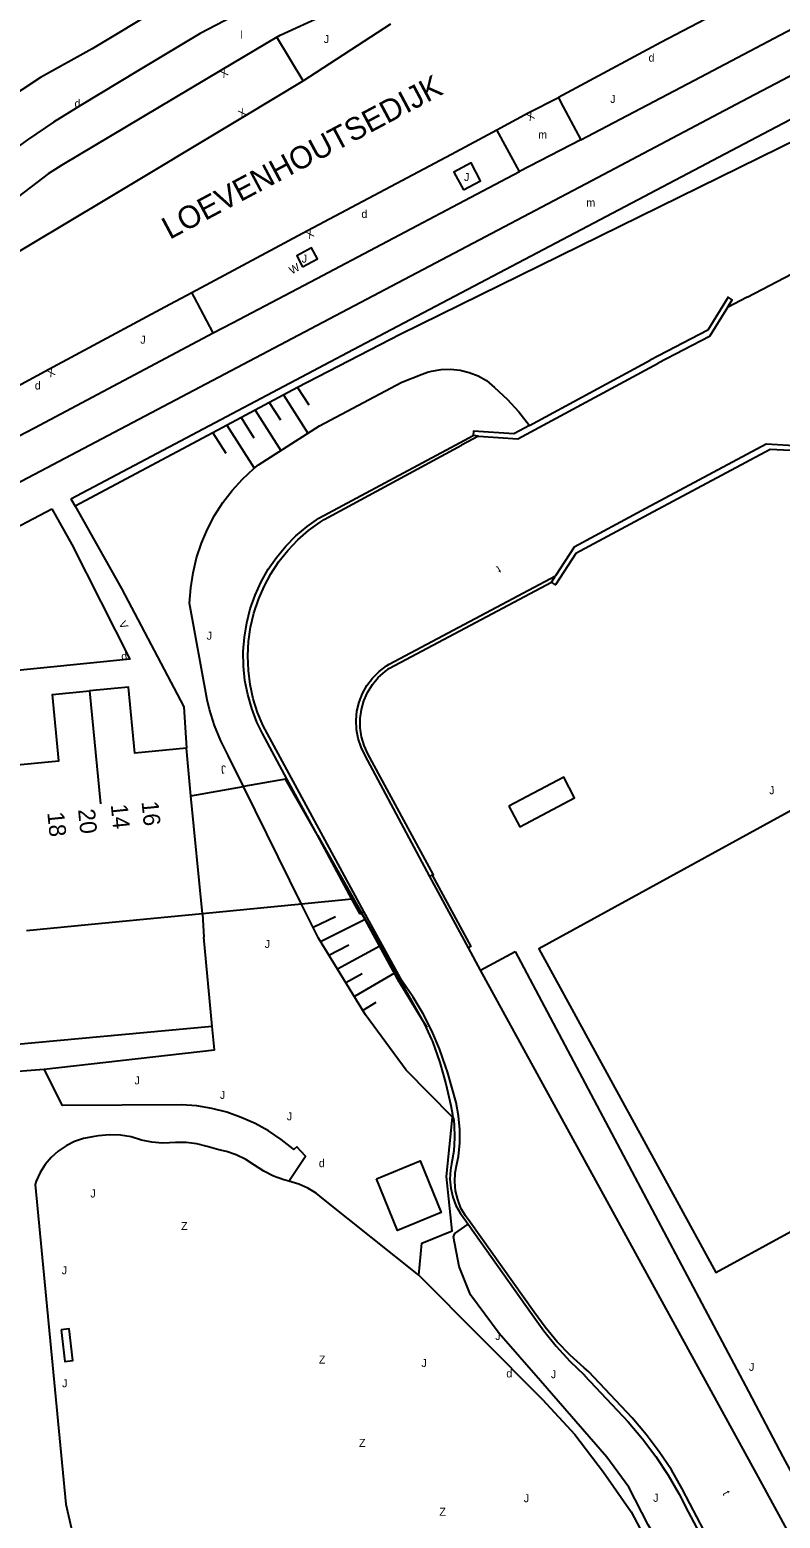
# Model space of a CAD drawing. Extents: x 134999 to 136502, y 457398 to 459002.
# Drawn here: x 136033.6 to 136080.5, y 457701.1 to 457794.1 of the extents above; entities that cross this region are included whole.
import ezdxf

# ---------------------------------------------------------------- set-up
doc = ezdxf.new("R2010")
doc.units = 0
for name, color, linetype in [('RI_DGTB_15', 7, 'Continuous'), ('RI_DGTB_18', 7, 'Continuous'), ('RI_DGTB_2', 7, 'Continuous'), ('RI_DGTB_29', 7, 'Continuous'), ('RI_DGTB_30', 7, 'Continuous'), ('RI_DGTB_31', 7, 'Continuous'), ('RI_DGTB_32', 7, 'Continuous'), ('RI_DGTB_35', 7, 'Continuous'), ('RI_DGTB_36', 7, 'Continuous'), ('RI_DGTB_37', 7, 'Continuous'), ('RI_DGTB_4', 7, 'Continuous'), ('RI_DGTB_43', 7, 'Continuous'), ('RI_DGTB_48', 7, 'Continuous'), ('RI_DGTB_49', 7, 'Continuous'), ('RI_DGTB_53', 7, 'Continuous'), ('RI_DGTB_54', 7, 'Continuous'), ('RI_DGTB_58', 7, 'Continuous'), ('RI_DGTB_6', 7, 'Continuous')]:
    doc.layers.add(name, color=color, linetype=linetype)

msp = doc.modelspace()

# ---------------------------------------------------------------- linework, layer by layer
at = {"layer": 'RI_DGTB_15'}
msp.add_line((136037.37, 457752.745), (136038.06, 457745.695), dxfattribs=at)
at = {"layer": 'RI_DGTB_18'}
for p, q in [((136049.494, 457771.241), (136051.018, 457768.855)), ((136050.378, 457771.713), (136051.077, 457770.619)), ((136047.728, 457770.296), (136049.335, 457767.781)), ((136048.61, 457770.772), (136049.305, 457769.684)), ((136045.956, 457769.359), (136047.651, 457766.707)), ((136046.845, 457769.826), (136047.65, 457768.566)), ((136045.078, 457768.883), (136045.898, 457767.6)), ((136050.625, 457739.432), (136046.998, 457746.769)), ((136052.745, 457738.628), (136051.357, 457737.97)), ((136054.604, 457738.462), (136051.81, 457737.077)), ((136053.579, 457736.861), (136052.337, 457736.219)), ((136055.516, 457736.792), (136052.87, 457735.36)), ((136061.812, 457735.294), (136063.968, 457736.473)), ((136054.42, 457735.078), (136053.4, 457734.504)), ((136056.429, 457735.111), (136053.925, 457733.643)), ((136055.264, 457733.284), (136054.451, 457732.786)), ((136060.05, 457726.105), (136060.113, 457726.041))]:
    msp.add_line(p, q, dxfattribs=at)
for points in [[(136106.177, 457800), (136085.466, 457789.129), (136056.796, 457775.016)], [(136056.796, 457775.016), (136050.378, 457771.713), (136045.078, 457768.883), (136036.475, 457764.296)], [(136058.167, 457772.539), (136058.497, 457772.667), (136058.753, 457772.736), (136059.34, 457772.833), (136059.934, 457772.851), (136060.526, 457772.789), (136061.103, 457772.649), (136061.657, 457772.432), (136062.177, 457772.143), (136062.692, 457771.714), (136063.475, 457770.977), (136064.2, 457770.185), (136064.864, 457769.341)], [(136046.998, 457746.769), (136046.035, 457748.712), (136045.574, 457749.636), (136045.186, 457750.593), (136044.873, 457751.578), (136044.72, 457752.186), (136043.632, 457758.228), (136043.698, 457759.184), (136043.843, 457760.132), (136044.067, 457761.064), (136044.367, 457761.975), (136044.743, 457762.857), (136045.19, 457763.705), (136045.707, 457764.512), (136046.289, 457765.274), (136046.933, 457765.984), (136047.634, 457766.639), (136047.927, 457766.882), (136051.737, 457769.313), (136056.882, 457772.041), (136058.167, 457772.539)], [(136060.05, 457726.105), (136057.171, 457729.051), (136054.631, 457732.501), (136051.677, 457737.292), (136050.625, 457739.432)], [(136063.968, 457736.473), (136078.546, 457708.97), (136080.695, 457704.886), (136101.064, 457667.235), (136120.849, 457630.867), (136122.138, 457628.364), (136122.744, 457627.053)], [(136123.733, 457602.393), (136120.854, 457608.26), (136113.226, 457622.174), (136108.621, 457631.115), (136104.943, 457638.994), (136101.264, 457646.446), (136083.989, 457678.217), (136077.85, 457689.911), (136077.399, 457690.806), (136074.236, 457697.397), (136072.278, 457700.64), (136071.067, 457702.994), (136069.704, 457704.875), (136065.561, 457709.646), (136062.974, 457712.597), (136061.189, 457715.009), (136060.471, 457716.789), (136060.125, 457718.639), (136060.201, 457718.837), (136061.046, 457719.422)]]:
    msp.add_lwpolyline(points, dxfattribs=at)
at = {"layer": 'RI_DGTB_2'}
msp.add_lwpolyline([(136096.988, 457758.601), (136096.548, 457759.448), (136091.535, 457756.892), (136093.868, 457752.395), (136088.931, 457749.695), (136089.018, 457749.537), (136065.444, 457736.642), (136076.51, 457716.41), (136097.04, 457727.64), (136100.779, 457725.365)], dxfattribs=at)
at = {"layer": 'RI_DGTB_32'}
msp.add_lwpolyline([(136035.608, 457712.829), (136035.839, 457710.846), (136036.336, 457710.904), (136036.105, 457712.887), (136035.608, 457712.829)], dxfattribs=at)
at = {"layer": 'RI_DGTB_4'}
for p, q in [((136043.716, 457746.202), (136043.426, 457749.167)), ((136044.436, 457738.829), (136043.716, 457746.202)), ((136044.436, 457738.829), (136038.786, 457738.278)), ((136038.786, 457738.278), (136033.434, 457737.757))]:
    msp.add_line(p, q, dxfattribs=at)
for points in [[(136032.42, 457748.095), (136035.457, 457748.389), (136035.055, 457752.518), (136037.37, 457752.745)], [(136043.426, 457749.167), (136040.206, 457748.853), (136039.808, 457752.985), (136037.37, 457752.745)]]:
    msp.add_lwpolyline(points, dxfattribs=at)
at = {"layer": 'RI_DGTB_48'}
for p, q in [((136043.716, 457746.202), (136046.998, 457746.769)), ((136051.619, 457743.727), (136054.38, 457738.871)), ((136050.625, 457739.432), (136044.436, 457738.829)), ((136053.776, 457739.739), (136050.625, 457739.432)), ((136044.436, 457738.829), (136044.512, 457737.353)), ((136054.38, 457738.871), (136056.832, 457734.569)), ((136045.047, 457731.785), (136044.512, 457737.353)), ((136056.832, 457734.569), (136058.171, 457732.193)), ((136058.171, 457732.193), (136058.449, 457731.727)), ((136060.067, 457726.277), (136060.05, 457726.105))]:
    msp.add_line(p, q, dxfattribs=at)
for points in [[(136051.619, 457743.727), (136049.629, 457747.224), (136046.998, 457746.769)], [(136057.944, 457716.231), (136058.149, 457718.239), (136060.038, 457719.005), (136059.673, 457722.41), (136060.05, 457726.105)], [(136049.835, 457722.112), (136049.508, 457722.197), (136048.868, 457722.429), (136048.26, 457722.735), (136047.691, 457723.11), (136047.139, 457723.467), (136046.547, 457723.754), (136045.925, 457723.967), (136045.456, 457724.074), (136044.729, 457724.288), (136044.079, 457724.45), (136043.414, 457724.533), (136042.745, 457724.536), (136042.369, 457724.503), (136041.946, 457724.495), (136041.277, 457724.549), (136040.619, 457724.681), (136039.981, 457724.89), (136039.305, 457724.993), (136038.623, 457725.015), (136037.942, 457724.957), (136037.569, 457724.891), (136036.991, 457724.78), (136036.434, 457724.591), (136035.907, 457724.329), (136035.421, 457723.998), (136034.984, 457723.603), (136034.605, 457723.154), (136034.29, 457722.657), (136034.045, 457722.121), (136033.971, 457721.909), (136035.903, 457701.937), (136036.459, 457699.463)], [(136057.944, 457716.231), (136052.002, 457720.983), (136051.529, 457721.366), (136051.011, 457721.683), (136050.455, 457721.93), (136049.835, 457722.112)], [(136057.944, 457716.231), (136065.689, 457708.481), (136067.693, 457706.277), (136069.486, 457703.938), (136071.216, 457701.453), (136071.805, 457700.347)]]:
    msp.add_lwpolyline(points, dxfattribs=at)
at = {"layer": 'RI_DGTB_49'}
msp.add_line((136058.449, 457731.727), (136058.421, 457731.701), dxfattribs=at)
at = {"layer": 'RI_DGTB_53'}
for p, q in [((136050.832, 457797.257), (136044.288, 457793.823)), ((136040.445, 457791.524), (136036.821, 457789.33)), ((136068.066, 457787.192), (136064.239, 457785.208)), ((136068.066, 457787.192), (136068.464, 457787.402)), ((136021.213, 457756.888), (136035.021, 457764.132))]:
    msp.add_line(p, q, dxfattribs=at)
for points in [[(136023.793, 457760.97), (136035.091, 457766.906), (136052.351, 457776.008), (136068.76, 457784.651), (136078.139, 457789.59), (136097.898, 457800)], [(136036.214, 457764.759), (136053.5, 457773.888), (136069.286, 457782.2), (136079.053, 457787.349), (136103.086, 457800)], [(136068.464, 457787.402), (136075.569, 457791.121), (136092.362, 457800)], [(136049.083, 457793.609), (136049.284, 457793.716), (136052.011, 457794.975)], [(136050.725, 457790.861), (136056.214, 457794.422)], [(136049.083, 457793.609), (136045.634, 457791.566), (136035.653, 457785.595), (136034.796, 457785.055), (136029.996, 457781.421)], [(136044.288, 457793.823), (136040.445, 457791.524)], [(136050.725, 457790.861), (136049.083, 457793.609)], [(136031.342, 457779.255), (136038.36, 457783.439), (136047.069, 457788.662), (136050.725, 457790.861)], [(136062.826, 457787.812), (136064.791, 457788.87), (136066.672, 457789.822)], [(136066.672, 457789.822), (136066.799, 457789.562), (136068.066, 457787.192)], [(136036.821, 457789.33), (136035.134, 457788.293), (136033.492, 457787.188), (136032.97, 457786.817)], [(136043.771, 457777.645), (136051.005, 457781.51), (136059.996, 457786.287), (136062.826, 457787.812)], [(136064.239, 457785.208), (136062.826, 457787.812)], [(136045.108, 457775.127), (136046.315, 457775.754), (136051.193, 457778.319), (136060.801, 457783.384), (136064.239, 457785.208)], [(136060.742, 457784.056), (136061.811, 457784.625), (136061.219, 457785.738), (136060.149, 457785.168), (136060.742, 457784.056)], [(136050.69, 457779.242), (136051.619, 457779.744), (136051.249, 457780.427), (136050.321, 457779.925), (136050.69, 457779.242)], [(136018.82, 457763.992), (136023.265, 457766.478), (136032.877, 457771.782), (136034.83, 457772.846), (136042.086, 457776.755), (136043.771, 457777.645)], [(136045.108, 457775.127), (136043.908, 457777.374), (136043.771, 457777.645)], [(136020.028, 457761.958), (136021.069, 457762.527), (136022.582, 457763.287), (136033.931, 457769.19), (136045.108, 457775.127)], [(136036.214, 457764.759), (136036.475, 457764.296)], [(136035.021, 457764.132), (136036.275, 457761.907)], [(136036.475, 457764.296), (136039.379, 457759.144)]]:
    msp.add_lwpolyline(points, dxfattribs=at)
at = {"layer": 'RI_DGTB_54'}
msp.add_line((136031.845, 457728.904), (136034.552, 457729.111), dxfattribs=at)
for points in [[(136049.819, 457800), (136043.73, 457796.624), (136041.882, 457795.467), (136037.542, 457792.862), (136034.323, 457791.076), (136030.788, 457788.763), (136026.961, 457786.044), (136020.907, 457780.612), (136016.279, 457776.789)], [(136086.028, 457800), (136079.534, 457796.67), (136073.076, 457793.27), (136066.672, 457789.822)], [(136036.275, 457761.907), (136039.898, 457754.737), (136021.074, 457752.839), (136020.823, 457755.06)], [(136039.379, 457759.144), (136043.274, 457751.751), (136043.426, 457749.167)], [(136045.047, 457731.785), (136023.134, 457729.758), (136022.437, 457736.685)], [(136034.552, 457729.111), (136045.182, 457730.316), (136045.047, 457731.785)], [(136049.835, 457722.112), (136050.864, 457723.67), (136050.333, 457724.256), (136050.149, 457724.086), (136050.099, 457724.13), (136049.351, 457724.723), (136048.556, 457725.252), (136047.719, 457725.712), (136046.847, 457726.101), (136045.946, 457726.416), (136045.021, 457726.654), (136044.079, 457726.814), (136043.128, 457726.894), (136035.696, 457726.84), (136034.552, 457729.111)]]:
    msp.add_lwpolyline(points, dxfattribs=at)
at = {"layer": 'RI_DGTB_58'}
for p, q in [((136078.46, 457777.349), (136121.852, 457800)), ((136078.46, 457777.349), (136077.242, 457776.713)), ((136064.864, 457769.341), (136072.413, 457773.421)), ((136060.527, 457768.278), (136061.342, 457768.705)), ((136061.672, 457768.666), (136060.625, 457768.1)), ((136061.672, 457768.666), (136061.342, 457768.705)), ((136066.245, 457759.544), (136066.498, 457759.936)), ((136051.619, 457743.727), (136049.713, 457747.252)), ((136053.776, 457739.739), (136051.619, 457743.727)), ((136058.784, 457741.225), (136058.639, 457741.159)), ((136061.047, 457736.69), (136058.639, 457741.159)), ((136054.28, 457738.807), (136053.776, 457739.739)), ((136054.28, 457738.807), (136054.38, 457738.871)), ((136054.38, 457738.871), (136054.519, 457738.97)), ((136056.746, 457734.521), (136054.38, 457738.871)), ((136056.91, 457734.618), (136054.519, 457738.97)), ((136061.812, 457735.294), (136061.047, 457736.69)), ((136056.746, 457734.521), (136056.832, 457734.569)), ((136056.746, 457734.521), (136058.171, 457732.193)), ((136056.832, 457734.569), (136056.91, 457734.618)), ((136058.171, 457732.193), (136058.421, 457731.701)), ((136060.113, 457726.041), (136060.067, 457726.277))]:
    msp.add_line(p, q, dxfattribs=at)
for points in [[(136077.242, 457776.713), (136077.537, 457777.191), (136077.282, 457777.348), (136076.007, 457775.281), (136072.413, 457773.421)], [(136077.242, 457776.713), (136076.116, 457774.887), (136072.915, 457773.232)], [(136061.672, 457768.666), (136064.146, 457768.498), (136072.915, 457773.232)], [(136064.864, 457769.341), (136063.892, 457768.816), (136061.369, 457768.987), (136061.342, 457768.705)], [(136049.713, 457747.252), (136048.183, 457750.081), (136047.835, 457750.801), (136047.509, 457751.646), (136047.26, 457752.516), (136047.088, 457753.404), (136046.995, 457754.305), (136046.983, 457755.21), (136047.05, 457756.113), (136047.196, 457757.006), (136047.421, 457757.883), (136047.722, 457758.737), (136048.098, 457759.56), (136048.544, 457760.348), (136049.059, 457761.093), (136049.637, 457761.789), (136050.274, 457762.432), (136050.966, 457763.016), (136051.706, 457763.537), (136060.527, 457768.278)], [(136081.767, 457768.041), (136079.65, 457768.157), (136072.141, 457764.149)], [(136054.519, 457738.97), (136048.218, 457750.569), (136047.874, 457751.401), (136047.605, 457752.26), (136047.413, 457753.14), (136047.3, 457754.033), (136047.267, 457754.933), (136047.313, 457755.832), (136047.439, 457756.723), (136047.644, 457757.6), (136047.926, 457758.455), (136048.283, 457759.282), (136048.711, 457760.074), (136049.208, 457760.825), (136049.77, 457761.528), (136050.392, 457762.179), (136051.069, 457762.773), (136051.797, 457763.303), (136052.043, 457763.462), (136060.625, 457768.1)], [(136081.767, 457768.041), (136082.419, 457768.005), (136082.403, 457767.705), (136079.909, 457767.842), (136072.298, 457763.781)], [(136072.298, 457763.781), (136067.755, 457761.325), (136066.497, 457759.381), (136066.245, 457759.544)], [(136072.141, 457764.149), (136067.656, 457761.726), (136066.498, 457759.936)], [(136058.639, 457741.159), (136054.606, 457748.708), (136054.349, 457749.225), (136054.167, 457749.772), (136054.061, 457750.34), (136054.035, 457750.916), (136054.089, 457751.491), (136054.221, 457752.053), (136054.43, 457752.591), (136054.712, 457753.095), (136055.06, 457753.555), (136055.468, 457753.963), (136055.929, 457754.31), (136056.102, 457754.417), (136066.498, 457759.936)], [(136058.784, 457741.225), (136058.863, 457741.261), (136054.768, 457748.815), (136054.533, 457749.336), (136054.373, 457749.884), (136054.291, 457750.45), (136054.289, 457751.021), (136054.367, 457751.587), (136054.523, 457752.137), (136054.754, 457752.659), (136055.055, 457753.145), (136055.422, 457753.583), (136055.846, 457753.966), (136056.127, 457754.168), (136066.245, 457759.544)], [(136058.784, 457741.225), (136061.2, 457736.776), (136061.047, 457736.69)], [(136121.392, 457626.305), (136098.946, 457667.306), (136079.053, 457703.844), (136061.812, 457735.294)], [(136084.948, 457682.81), (136074.89, 457701.98), (136074.417, 457702.896), (136073.732, 457704.069), (136072.979, 457705.199), (136072.161, 457706.283), (136071.281, 457707.317), (136068.572, 457710.21), (136068.291, 457710.443), (136067.42, 457711.233), (136066.605, 457712.081), (136065.849, 457712.982), (136065.156, 457713.932), (136061.165, 457719.553), (136060.867, 457719.946), (136060.588, 457720.436), (136060.382, 457720.96), (136060.252, 457721.508), (136060.2, 457722.069), (136060.229, 457722.632), (136060.337, 457723.185), (136060.422, 457723.66), (136060.508, 457724.502), (136060.515, 457725.349), (136060.441, 457726.193), (136060.289, 457727.026), (136059.741, 457728.945), (136059.65, 457729.243), (136059.246, 457730.386), (136058.768, 457731.499), (136058.218, 457732.579), (136057.598, 457733.62), (136056.91, 457734.618)], [(136058.421, 457731.701), (136058.75, 457730.968), (136058.803, 457730.832), (136059.265, 457729.524), (136059.651, 457728.191), (136059.959, 457726.838), (136060.067, 457726.277)], [(136060.113, 457726.041), (136060.155, 457725.646), (136060.184, 457724.825), (136060.132, 457724.005), (136060.001, 457723.194), (136059.933, 457722.812), (136059.899, 457722.244), (136059.946, 457721.678), (136060.072, 457721.124), (136060.274, 457720.593), (136060.548, 457720.095), (136060.89, 457719.641), (136061.046, 457719.422)], [(136061.046, 457719.422), (136065.038, 457713.791), (136065.756, 457712.77), (136066.538, 457711.796), (136067.381, 457710.875), (136068.281, 457710.01), (136068.315, 457709.979), (136071.033, 457707.079), (136071.927, 457706.016), (136072.758, 457704.904), (136073.524, 457703.746), (136074.222, 457702.546), (136074.784, 457701.446), (136092.963, 457667.226), (136102.393, 457649.868)]]:
    msp.add_lwpolyline(points, dxfattribs=at)
at = {"layer": 'RI_DGTB_6'}
for points in [[(136063.579, 457745.549), (136064.261, 457744.258), (136067.686, 457746.067), (136067.004, 457747.358), (136063.579, 457745.549)], [(136055.306, 457722.27), (136058.035, 457723.376), (136059.344, 457720.146), (136056.615, 457719.04), (136055.306, 457722.27)]]:
    msp.add_lwpolyline(points, dxfattribs=at)

# ---------------------------------------------------------------- texts
at = {"layer": 'RI_DGTB_29'}
for p in [(136072.309, 457792.071), (136054.363, 457782.3), (136033.958, 457771.583), (136051.706, 457722.987), (136063.421, 457709.849)]:
    msp.add_text('d', height=0.5, dxfattribs=at).set_placement(p)
for rotation, p in [(359.99963, (136036.44, 457789.21)), (5.76523, (136039.38, 457754.646))]:
    msp.add_text('d', height=0.5, rotation=rotation, dxfattribs=at).set_placement(p)
at = {"layer": 'RI_DGTB_30'}
for s, height, rotation, p in [('X', 0.5, 210.64597, (136045.849, 457791.693)), ('X', 0.5, 30.95456, (136046.855, 457788.533)), ('X', 0.5, 208.30869, (136065.011, 457788.989)), ('X', 0.5, 208.11674, (136051.225, 457781.628)), ('W', 0.5, 29.14225, (136050.018, 457778.761)), ('X', 0.5, 208.589, (136035.05, 457772.966)), ('V', 0.499, 297.01724, (136039.174, 457756.962))]:
    msp.add_text(s, height=height, rotation=rotation, dxfattribs=at).set_placement(p)
at = {"layer": 'RI_DGTB_31'}
for p in [(136052.014, 457793.235), (136069.914, 457789.49), (136060.774, 457784.611), (136050.636, 457779.512), (136040.548, 457774.444), (136044.694, 457755.947), (136048.321, 457736.683), (136040.192, 457728.161), (136045.524, 457727.257), (136049.705, 457725.918), (136037.429, 457721.094), (136035.635, 457716.294), (136062.726, 457712.191), (136058.115, 457710.502), (136078.582, 457710.261), (136035.661, 457709.234), (136066.206, 457709.803), (136064.512, 457702.054), (136072.598, 457702.077)]:
    msp.add_text('J', height=0.5, dxfattribs=at).set_placement(p)
for height, rotation, p in [(0.5, 185.61159, (136045.893, 457748.104)), (0.499, 5.53065, (136079.864, 457746.277))]:
    msp.add_text('J', height=height, rotation=rotation, dxfattribs=at).set_placement(p)
at = {"layer": 'RI_DGTB_32'}
for p in [(136043.097, 457719.06), (136051.706, 457710.716), (136054.217, 457705.513), (136059.238, 457701.206)]:
    msp.add_text('Z', height=0.5, dxfattribs=at).set_placement(p)
at = {"layer": 'RI_DGTB_35'}
msp.add_text('16', height=1.054, rotation=275.5548, dxfattribs=at).set_placement((136040.625, 457745.825))
at = {"layer": 'RI_DGTB_36'}
for s, rotation, p in [('18', 275.5881, (136034.736, 457745.147)), ('20', 275.5881, (136036.657, 457745.335)), ('14', 275.5548, (136038.703, 457745.638))]:
    msp.add_text(s, height=1.054, rotation=rotation, dxfattribs=at).set_placement(p)
at = {"layer": 'RI_DGTB_37'}
msp.add_text('LOEVENHOUTSEDIJK', height=1.40009, rotation=28.04398, dxfattribs=at).set_placement((136042.387, 457780.93))
at = {"layer": 'RI_DGTB_43'}
for s, p in [('l', (136046.789, 457793.503)), ('m', (136065.411, 457787.259)), ('m', (136068.419, 457783.011))]:
    msp.add_text(s, height=0.5, dxfattribs=at).set_placement(p)
for rotation, p in [(207.84251, (136062.919, 457760.589)), (298.18649, (136076.912, 457702.602))]:
    msp.add_text('t', height=0.5, rotation=rotation, dxfattribs=at).set_placement(p)

doc.saveas('drawing.dxf')
